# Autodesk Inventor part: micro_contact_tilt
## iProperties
Created: 2011-01
Part Number: micro_contact_tilt
Document SubType Name: Modeling
Designer: eric
Density: 1 g/cm^3
Mass: 1.28072 g
Surface Area: 11.93 cm^2
Volume: 1.28072 cm^3
Author: eric
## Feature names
1. Base1
